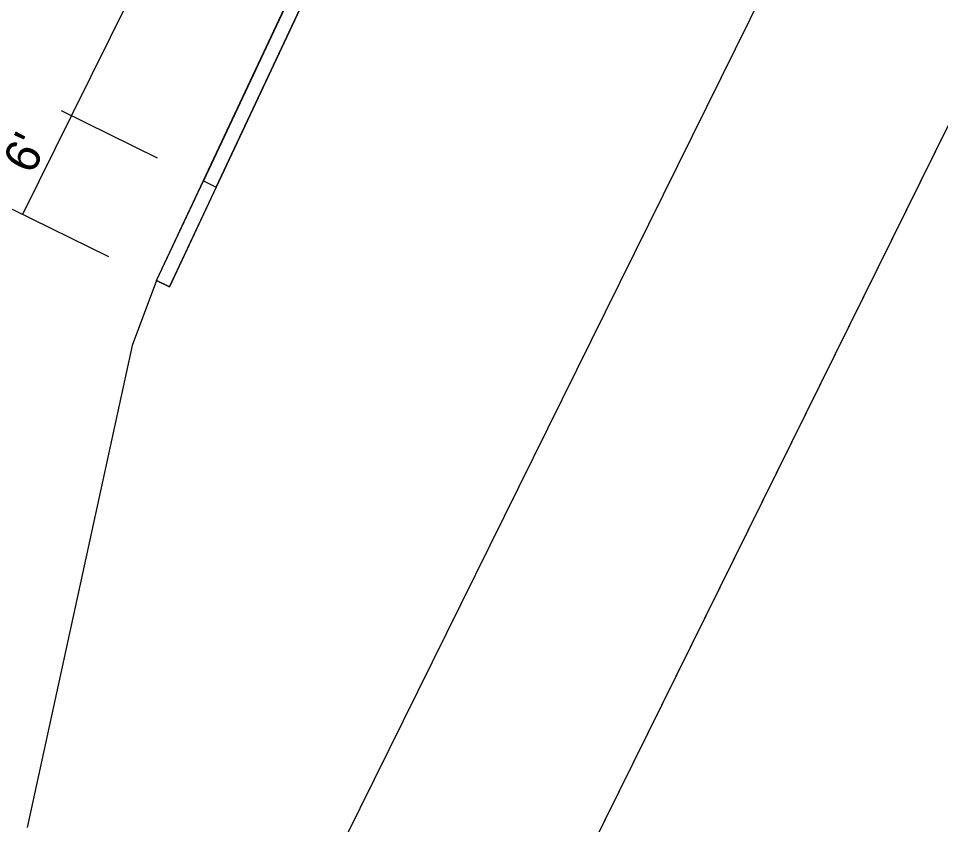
# Model space of a CAD drawing. Extents: x 14104283 to 14129344, y 8637090 to 8673339.
# Drawn here: x 14118129.1 to 14118342.5, y 8668202 to 8668388.5 of the extents above; entities that cross this region are included whole.
import ezdxf

# ---------------------------------------------------------------- set-up
doc = ezdxf.new("R2010")
doc.units = 0
for name, color, linetype in [('Default', 7, 'Continuous'), ('dsnNonPlotable', 7, 'Continuous'), ('dsnStgShadingPrevPav', 7, 'Continuous'), ('dsnTextFinalPlan', 7, 'Continuous'), ('dsnTextOverlapEven', 7, 'Continuous'), ('TC_SubstrataExistingPavement', 7, 'Continuous'), ('Terrain', 7, 'Continuous')]:
    doc.layers.add(name, color=color, linetype=linetype)

msp = doc.modelspace()

# ---------------------------------------------------------------- linework, layer by layer
at = {"layer": 'Default'}
msp.add_lwpolyline([(14118174.89, 8668349.44), (14118236.5, 8668480.6), (14118249.33, 8668507.9), (14118246.34, 8668509.38), (14118233.51, 8668482.07), (14118171.9, 8668350.92)], close=True, dxfattribs=at)
at = {"layer": 'dsnNonPlotable'}
msp.add_lwpolyline([(14118092.03, 8667853.71), (14118786.76, 8669258.84), (14119692.14, 8668811.2), (14118997.41, 8667406.07)], close=True, dxfattribs=at)
at = {"layer": 'dsnStgShadingPrevPav'}
msp.add_lwpolyline([(14118161.08, 8668327.89), (14118171.9, 8668350.92), (14118174.89, 8668349.44), (14118164.07, 8668326.41)], close=True, dxfattribs=at)
at = {"layer": 'dsnTextFinalPlan'}
for p, q in [((14118141.41, 8668365.99), (14118205.63, 8668495.86)), ((14118138.96, 8668367.2), (14118161.19, 8668356.21)), ((14118130.14, 8668343.18), (14118141.41, 8668365.99)), ((14118127.69, 8668344.4), (14118149.92, 8668333.4))]:
    msp.add_line(p, q, dxfattribs=at)
for points in [[(14117870.36, 8667977.42), (14118384.92, 8669018.16), (14118565.56, 8668928.85), (14118050.99, 8667888.12)], [(14118092.03, 8667853.71), (14118606.59, 8668894.44), (14118787.23, 8668805.14), (14118272.66, 8667764.4)]]:
    msp.add_lwpolyline(points, close=True, dxfattribs=at)
at = {"layer": 'dsnTextOverlapEven'}
msp.add_lwpolyline([(14117870.36, 8667977.42), (14118384.92, 8669018.16), (14118565.56, 8668928.85), (14118050.99, 8667888.12)], close=True, dxfattribs=at)
at = {"layer": 'TC_SubstrataExistingPavement'}
for p, q in [((14118164.07, 8668326.41), (14118236.5, 8668480.6)), ((14118171.9, 8668350.92), (14118174.89, 8668349.44)), ((14118161.08, 8668327.89), (14118164.07, 8668326.41))]:
    msp.add_line(p, q, dxfattribs=at)
at = {"layer": 'Terrain'}
for p, q in [((14118161.08, 8668327.89), (14118233.51, 8668482.07)), ((14118161.08, 8668327.89), (14118155.41, 8668312.82)), ((14118155.41, 8668312.82), (14118131.11, 8668201.36))]:
    msp.add_line(p, q, dxfattribs=at)

# ---------------------------------------------------------------- texts
at = {"layer": 'dsnTextFinalPlan'}
msp.add_text("6'", height=8, rotation=63.6911, dxfattribs=at).set_placement((14118132.36, 8668352.15))

doc.saveas('drawing.dxf')
